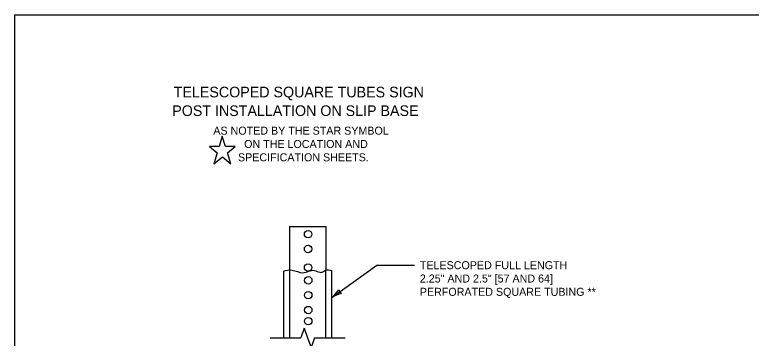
# Model space of a CAD drawing. Extents: x 49940 to 50043, y 49986 to 50011.
# Drawn here: x 49999.38 to 50004.91, y 49996.57 to 49999 of the extents above; entities that cross this region are included whole.
import ezdxf

# ---------------------------------------------------------------- set-up
doc = ezdxf.new("R2010")
doc.units = 0
for name, color, linetype in [('Level 1', 7, 'Continuous'), ('Level 2', 7, 'Continuous'), ('Level 3', 7, 'Continuous'), ('Level 4', 7, 'Continuous'), ('Level 6', 7, 'Continuous')]:
    doc.layers.add(name, color=color, linetype=linetype)

msp = doc.modelspace()

# ---------------------------------------------------------------- linework, layer by layer
at = {"layer": 'Level 1'}
msp.add_line((50001.4433, 49997.4092), (50001.7158, 49997.4092), dxfattribs=at)
msp.add_lwpolyline([(49999.3835, 49998.9992), (50016.7501, 49998.9992), (50016.7501, 49987.7988), (49999.3835, 49987.7988)], close=True, dxfattribs=at)
for points in [[(50001.4433, 49997.4092), (50001.4433, 49997.0798)], [(50001.7158, 49997.4092), (50001.7159, 49997.0813)], [(50001.3979, 49997.0743), (50001.3981, 49996.5734)], [(50001.7612, 49996.5735), (50001.7612, 49997.0784)]]:
    msp.add_lwpolyline(points, dxfattribs=at)
for centre in [(50001.5829, 49997.3522), (50001.5829, 49997.3522), (50001.5829, 49997.2406), (50001.5829, 49997.1014), (50001.5844, 49997.0053), (50001.5844, 49997.0053), (50001.5844, 49996.8938), (50001.5844, 49996.8938), (50001.5844, 49996.7822), (50001.5844, 49996.6984)]:
    msp.add_circle(centre, 0.0277, dxfattribs=at)
msp.add_spline([(50001.3986, 49997.0735), (50001.4634, 49997.0826), (50001.5431, 49997.0621), (50001.6303, 49997.0796), (50001.6714, 49997.0657), (50001.6857, 49997.0663), (50001.7144, 49997.0814), (50001.7611, 49997.0784)], degree=3, dxfattribs=at)
at = {"layer": 'Level 2'}
for p, q in [((50000.9401, 49998.0878), (50000.9163, 49998.0095)), ((50000.9641, 49998.0093), (50000.9401, 49998.0878)), ((50000.8451, 49998.0094), (50000.9019, 49997.9628)), ((50000.9164, 49998.0094), (50000.8451, 49998.0094)), ((50001.0353, 49998.0094), (50000.9641, 49998.0094)), ((50000.9785, 49997.9628), (50001.0353, 49998.0094)), ((50000.9019, 49997.9628), (50000.8766, 49997.8794)), ((50000.8766, 49997.8794), (50000.9402, 49997.9315)), ((50000.9401, 49997.9835), (50000.9401, 49997.9835)), ((50000.9402, 49997.9315), (50001.0037, 49997.8794)), ((50001.0037, 49997.8794), (50000.9785, 49997.9628))]:
    msp.add_line(p, q, dxfattribs=at)
at = {"layer": 'Level 3'}
for p, q in [((50001.7612, 49996.876), (50002.0997, 49997.119)), ((50002.0997, 49997.119), (50002.381, 49997.119))]:
    msp.add_line(p, q, dxfattribs=at)
for centre, radius, start, end in [((50001.6161, 49997.0583), 0.233, 308.5009, 327.7507), ((50001.8833, 49996.6902), 0.2223, 103.1296, 123.3131), ((50001.8653, 49996.9508), 0.0548, 197.8124, 233.5347)]:
    msp.add_arc(centre, radius, start, end, dxfattribs=at)
at = {"layer": 'Level 4'}
for points in [[(50001.4433, 49997.0798), (50001.4435, 49996.5734)], [(50001.7159, 49996.5735), (50001.7159, 49997.0813)]]:
    msp.add_lwpolyline(points, dxfattribs=at)
at = {"layer": 'Level 6'}
for p, q in [((50001.5537, 49996.6465), (50001.5278, 49996.5734)), ((50001.5537, 49996.6465), (50001.5796, 49996.5734)), ((50001.2981, 49996.5734), (50001.5278, 49996.5734)), ((50001.5796, 49996.5734), (50001.6055, 49996.5003)), ((50001.6314, 49996.5734), (50001.6055, 49996.5003)), ((50001.6314, 49996.5735), (50001.8612, 49996.5735))]:
    msp.add_line(p, q, dxfattribs=at)

# ---------------------------------------------------------------- texts
at = {"layer": 'Level 2'}
for s, height, p in [('TELESCOPED SQUARE TUBES SIGN', 0.0799, (50000.5757, 49998.3788)), ('POST INSTALLATION ON SLIP BASE', 0.0799, (50000.5646, 49998.2388)), ('AS NOTED BY THE STAR SYMBOL', 0.06, (50000.8727, 49998.0988)), ('ON THE LOCATION AND', 0.06, (50001.1034, 49997.9988)), (' SPECIFICATION SHEETS.', 0.06, (50001.0353, 49997.8988)), ('TELESCOPED FULL LENGTH', 0.06, (50002.421, 49997.089)), ('2.25" AND 2.5" [57 AND 64] ', 0.06, (50002.421, 49996.989)), ('PERFORATED SQUARE TUBING **', 0.06, (50002.421, 49996.889))]:
    msp.add_text(s, height=height, dxfattribs=at).set_placement(p)

doc.saveas('drawing.dxf')
